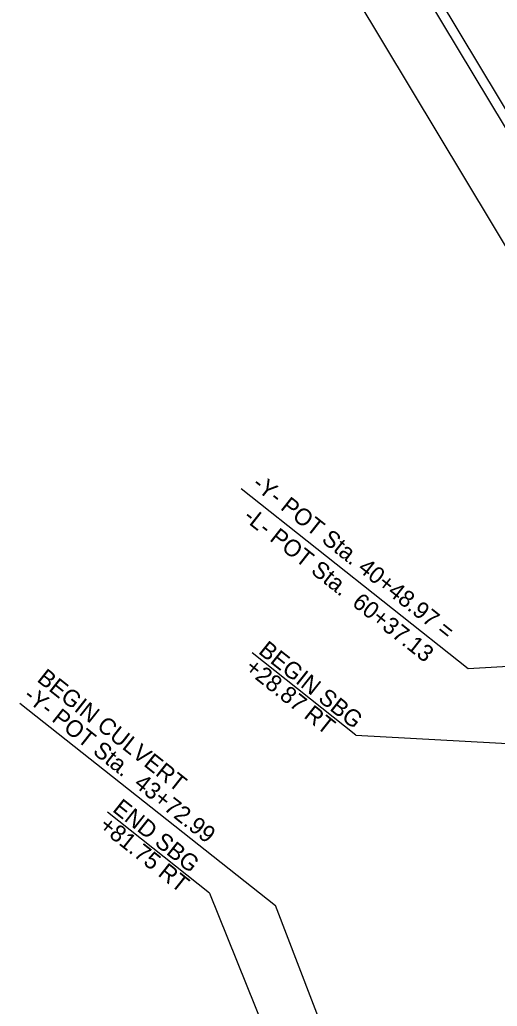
# Model space of a CAD drawing. Extents: x 1778969 to 1790720, y 807089 to 817794.
# Drawn here: x 1781432.5 to 1781631.5, y 813220.7 to 813631.7 of the extents above; entities that cross this region are included whole.
import ezdxf

# ---------------------------------------------------------------- set-up
doc = ezdxf.new("R2010")
doc.units = 0
for name, color, linetype in [('Prop Dimension', 7, 'Continuous'), ('Prop Dimension Text', 7, 'Continuous'), ('Prop EOT', 7, 'Continuous'), ('Prop Horizontal Alignment Station Label', 7, 'Continuous'), ('Prop Paved Shoulder', 7, 'Continuous')]:
    doc.layers.add(name, color=color, linetype=linetype)

msp = doc.modelspace()

# ---------------------------------------------------------------- linework, layer by layer
at = {"layer": 'Prop Dimension'}
for p, q in [((1781562.09, 813658.39), (1781783.55, 813289.81)), ((1781572.6, 813333.63), (1781529.31, 813367.91)), ((1781572.6, 813333.63), (1781726.39, 813325.16)), ((1781511.61, 813267.89), (1781469.03, 813301.6)), ((1781511.61, 813267.89), (1781567.85, 813128.14))]:
    msp.add_line(p, q, dxfattribs=at)
at = {"layer": 'Prop EOT'}
msp.add_line((1781587.3, 813673.54), (1781757.26, 813390.67), dxfattribs=at)
msp.add_open_spline([(1781463.3, 813949.03), (1781464.17, 813947.59), (1781465.05, 813946.15), (1781465.92, 813944.71), (1781474.8, 813929.99), (1781483.67, 813915.26), (1781492.5, 813900.51), (1781500.58, 813887.01), (1781508.59, 813873.47), (1781516.69, 813859.98), (1781525.21, 813845.83), (1781533.74, 813831.69), (1781542.26, 813817.54), (1781551.3, 813802.52), (1781560.33, 813787.49), (1781569.37, 813772.46), (1781578.14, 813757.89), (1781587.14, 813743.46), (1781595.91, 813728.89), (1781604.33, 813714.9), (1781612.49, 813700.76), (1781620.9, 813686.76), (1781629.44, 813672.57), (1781637.98, 813658.38), (1781646.54, 813644.19), (1781655.1, 813630), (1781663.72, 813615.84), (1781672.26, 813601.63), (1781680.69, 813587.61), (1781689, 813573.52), (1781697.41, 813559.48), (1781705.95, 813545.23), (1781714.52, 813530.99), (1781723.07, 813516.73), (1781731.64, 813502.44), (1781740.12, 813488.1), (1781748.7, 813473.81), (1781757.55, 813459.07), (1781766.63, 813444.47), (1781775.52, 813429.74), (1781784.14, 813415.46), (1781792.67, 813401.11), (1781801.32, 813386.83), (1781809.96, 813372.55), (1781818.65, 813358.29), (1781827.3, 813344.02), (1781835.99, 813329.66), (1781844.67, 813315.3), (1781853.35, 813300.93), (1781861.54, 813287.37), (1781869.6, 813273.73), (1781877.8, 813260.18), (1781886.68, 813245.53), (1781895.77, 813231.01), (1781904.68, 813216.38), (1781913.11, 813202.51), (1781921.54, 813188.63), (1781929.97, 813174.75), (1781938.85, 813160.12), (1781947.7, 813145.46), (1781956.59, 813130.83), (1781964.95, 813117.07), (1781973.52, 813103.43), (1781982.19, 813089.85), (1781991.2, 813075.72), (1782000.27, 813061.63), (1782009.36, 813047.54), (1782018.57, 813033.28), (1782027.8, 813019.03), (1782037.07, 813004.8), (1782046.22, 812990.76), (1782055.4, 812976.74), (1782064.84, 812962.89), (1782074.16, 812949.23), (1782083.5, 812935.58), (1782092.82, 812921.91), (1782102.18, 812908.19), (1782111.54, 812894.47), (1782120.9, 812880.75), (1782130.3, 812866.98), (1782139.85, 812853.32), (1782149.42, 812839.67), (1782158.88, 812826.17), (1782168.45, 812812.74), (1782178.15, 812799.41), (1782187.7, 812786.29), (1782197.57, 812773.41), (1782207.08, 812760.26), (1782216.45, 812747.28), (1782225.83, 812734.3), (1782235.2, 812721.32)], degree=3, dxfattribs=at)
at = {"layer": 'Prop Horizontal Alignment Station Label'}
for p, q in [((1781524.73, 813436.38), (1781619.36, 813361.45)), ((1781619.36, 813361.45), (1781795.46, 813371.12)), ((1781432.5, 813346.97), (1781539.01, 813262.64)), ((1781595.28, 813116.48), (1781539.01, 813262.64))]:
    msp.add_line(p, q, dxfattribs=at)
at = {"layer": 'Prop Paved Shoulder'}
msp.add_line((1781583.87, 813671.48), (1781749.71, 813395.47), dxfattribs=at)

# ---------------------------------------------------------------- texts
at = {"layer": 'Prop Dimension Text'}
for s, p in [('BEGIN SBG', (1781531.56, 813367.98)), ('+28.87 RT', (1781525.85, 813360.8)), ('END SBG', (1781470.77, 813302.16)), ('+81.75 RT', (1781465.06, 813294.98))]:
    msp.add_text(s, height=7, rotation=321.5251, dxfattribs=at).set_placement(p)
at = {"layer": 'Prop Horizontal Alignment Station Label'}
for s, rotation, p in [('-Y- POT Sta. 40+48.97 =', 321.6309, (1781528.92, 813437.32)), ('-L- POT Sta.  60+37.13', 321.7606, (1781525.23, 813423.67)), ('BEGIN CULVERT ', 321.6309, (1781439.3, 813356.35)), ('-Y- POT Sta.  43+72.99', 321.6309, (1781433.6, 813349.15))]:
    msp.add_text(s, height=7, rotation=rotation, dxfattribs=at).set_placement(p)

doc.saveas('drawing.dxf')
